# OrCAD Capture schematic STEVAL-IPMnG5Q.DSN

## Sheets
1 Inputs: size A4; title: STEVAL-IPMnG5Q; rev: 1.0; note: Draft
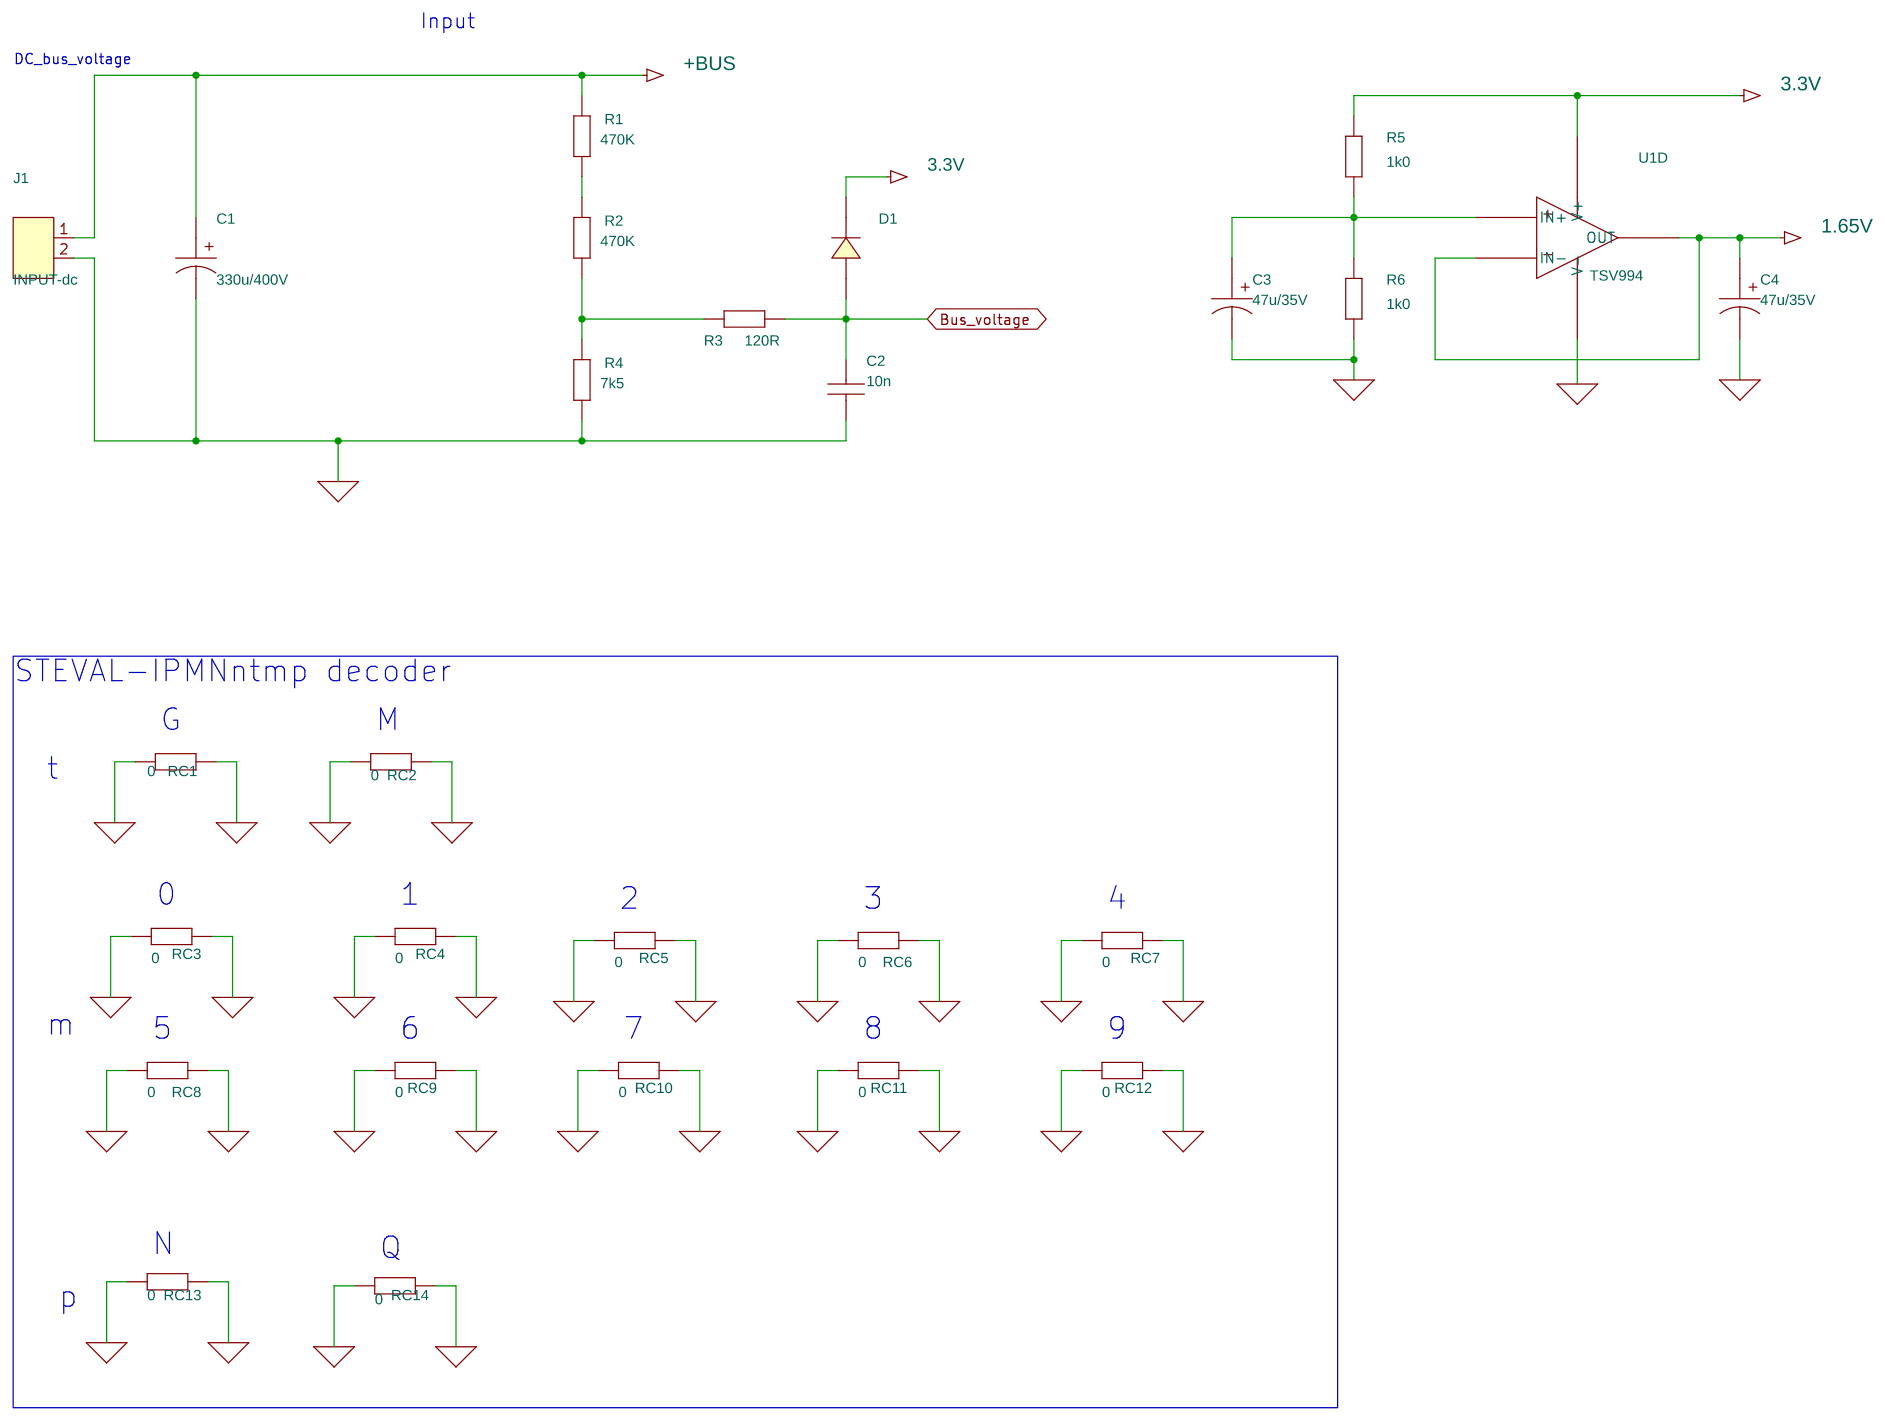
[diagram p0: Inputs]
2 Connectors: size A4
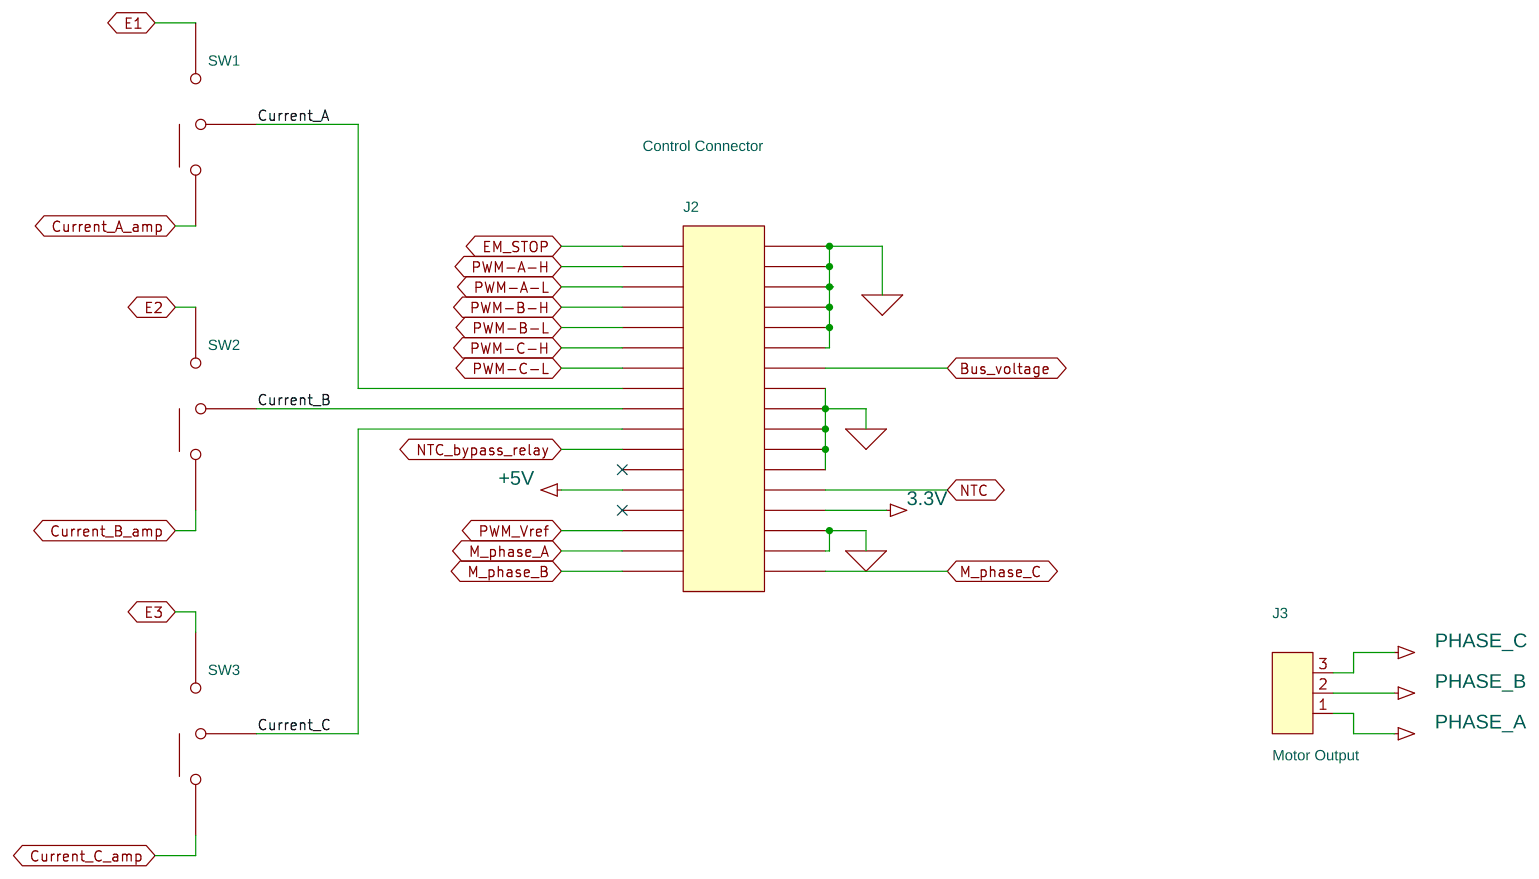
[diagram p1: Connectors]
3 Module: size Custom
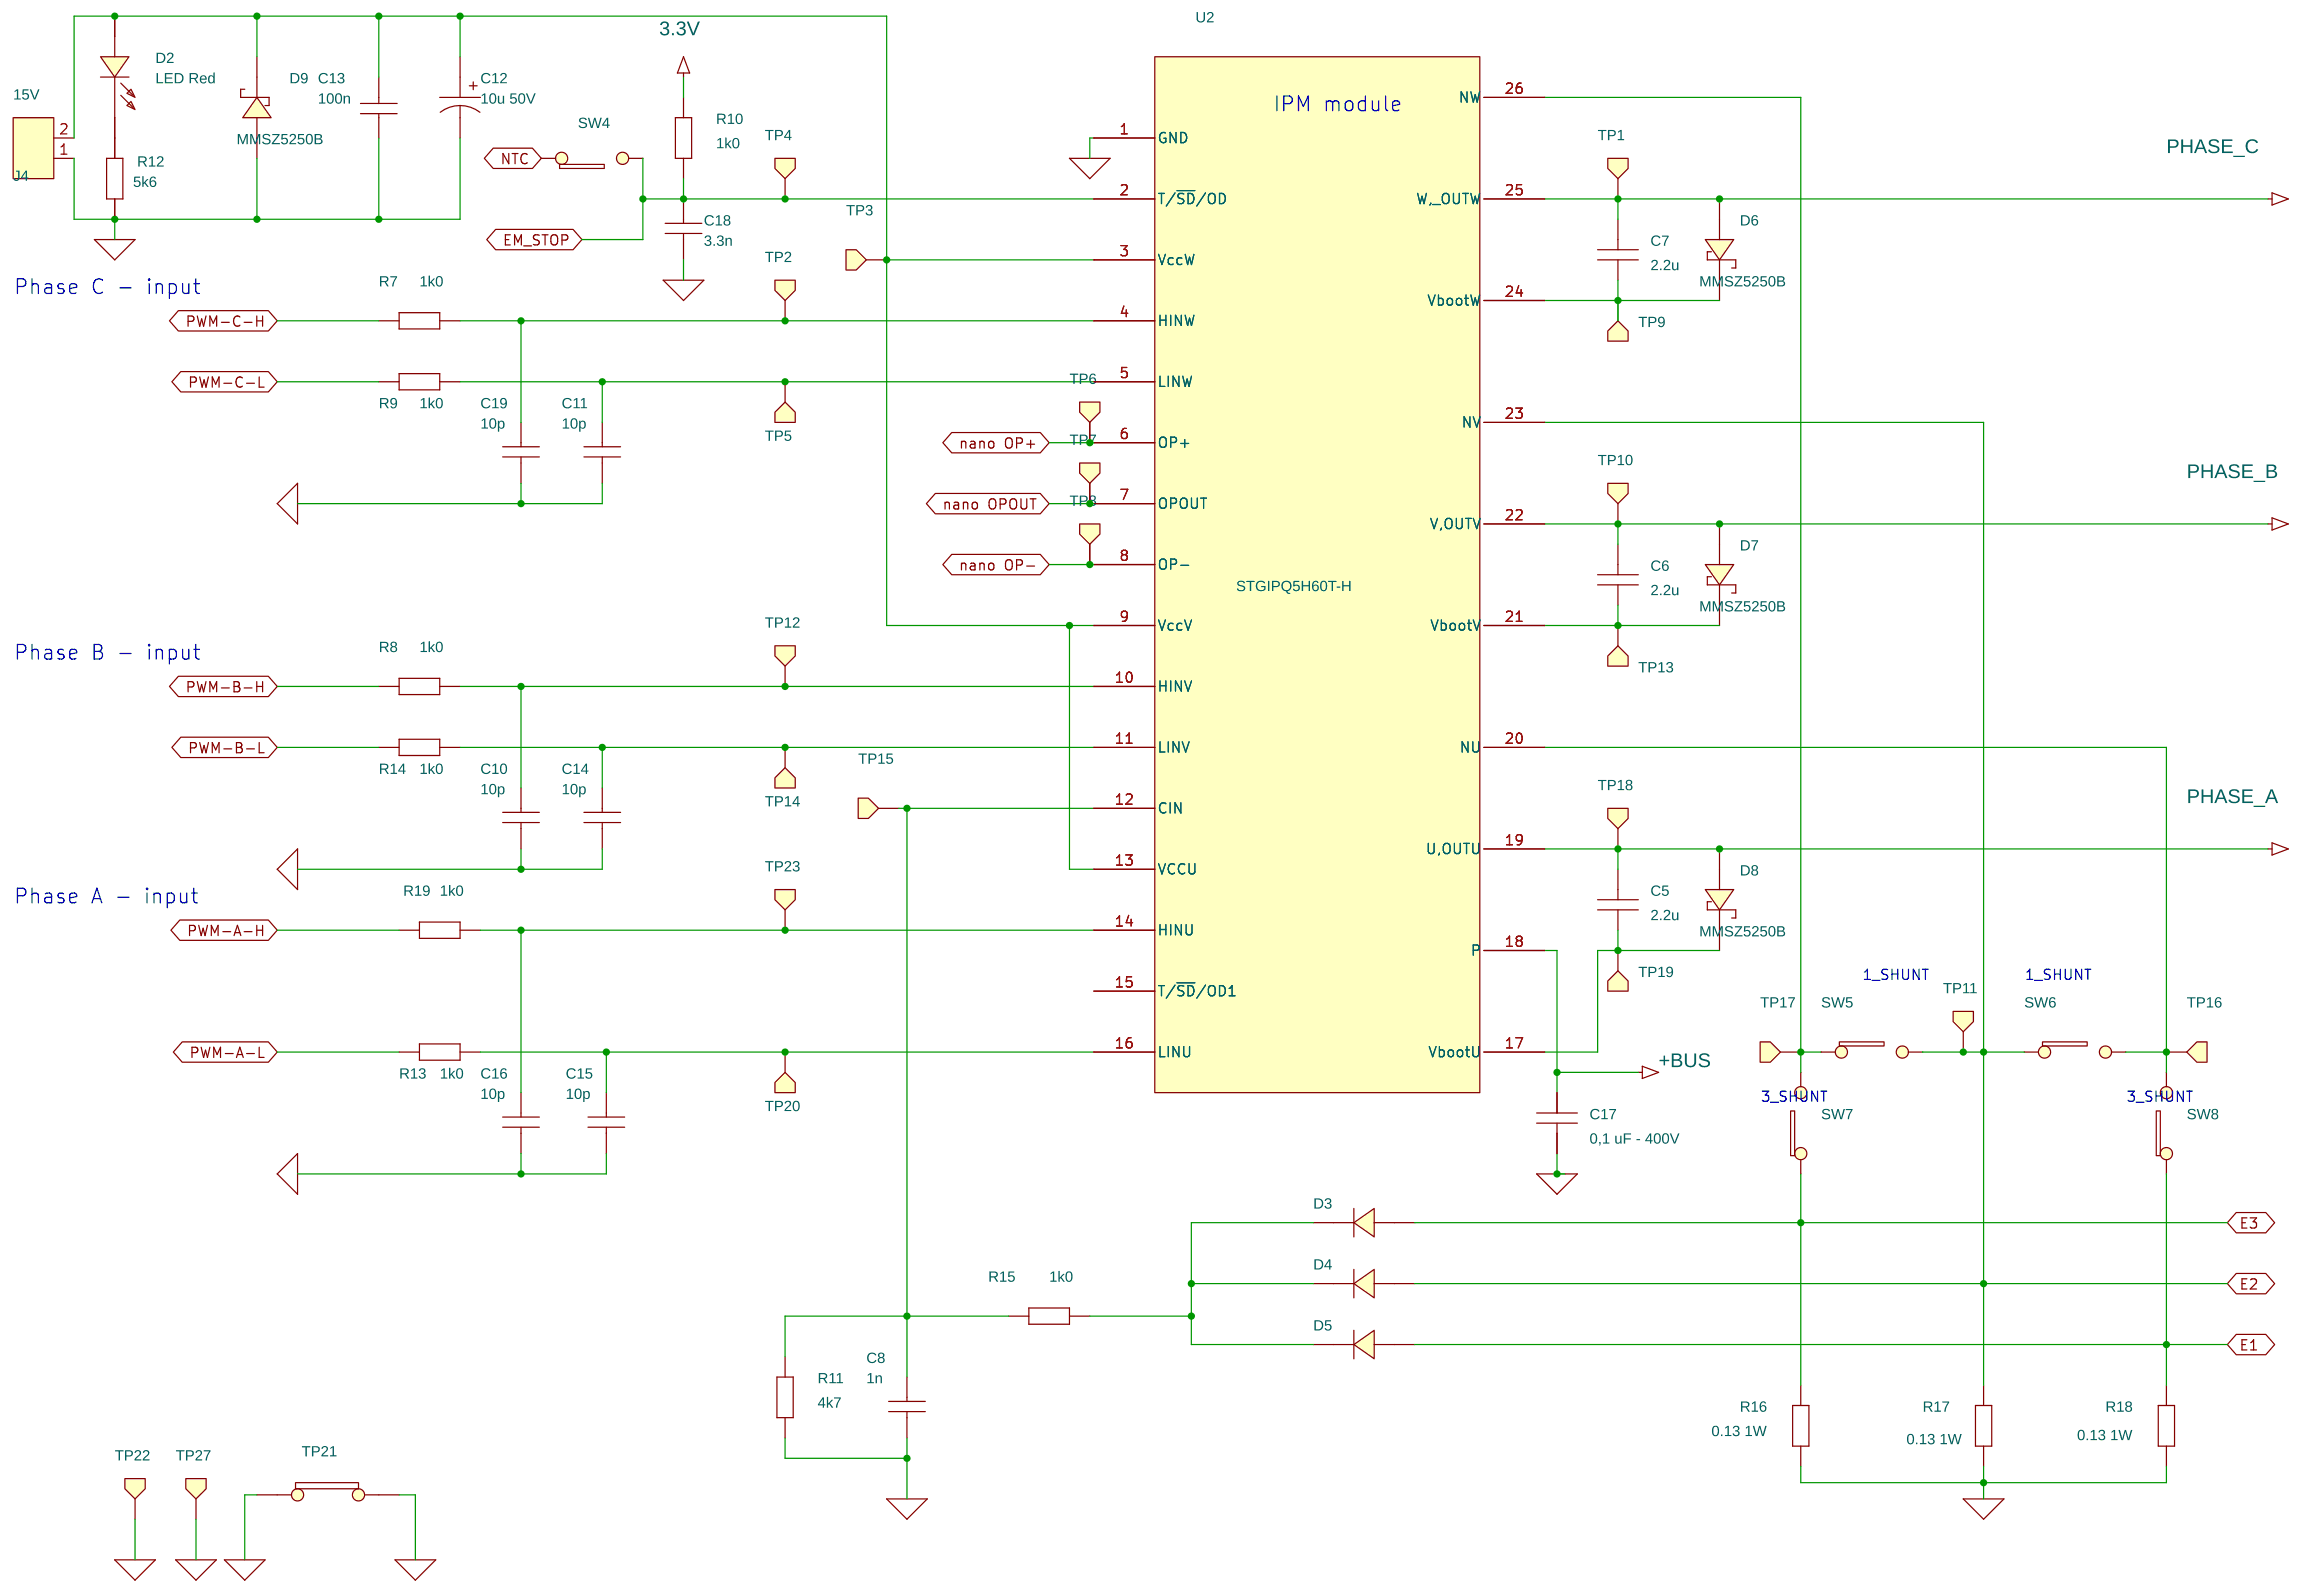
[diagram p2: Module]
4 Sensing: size A
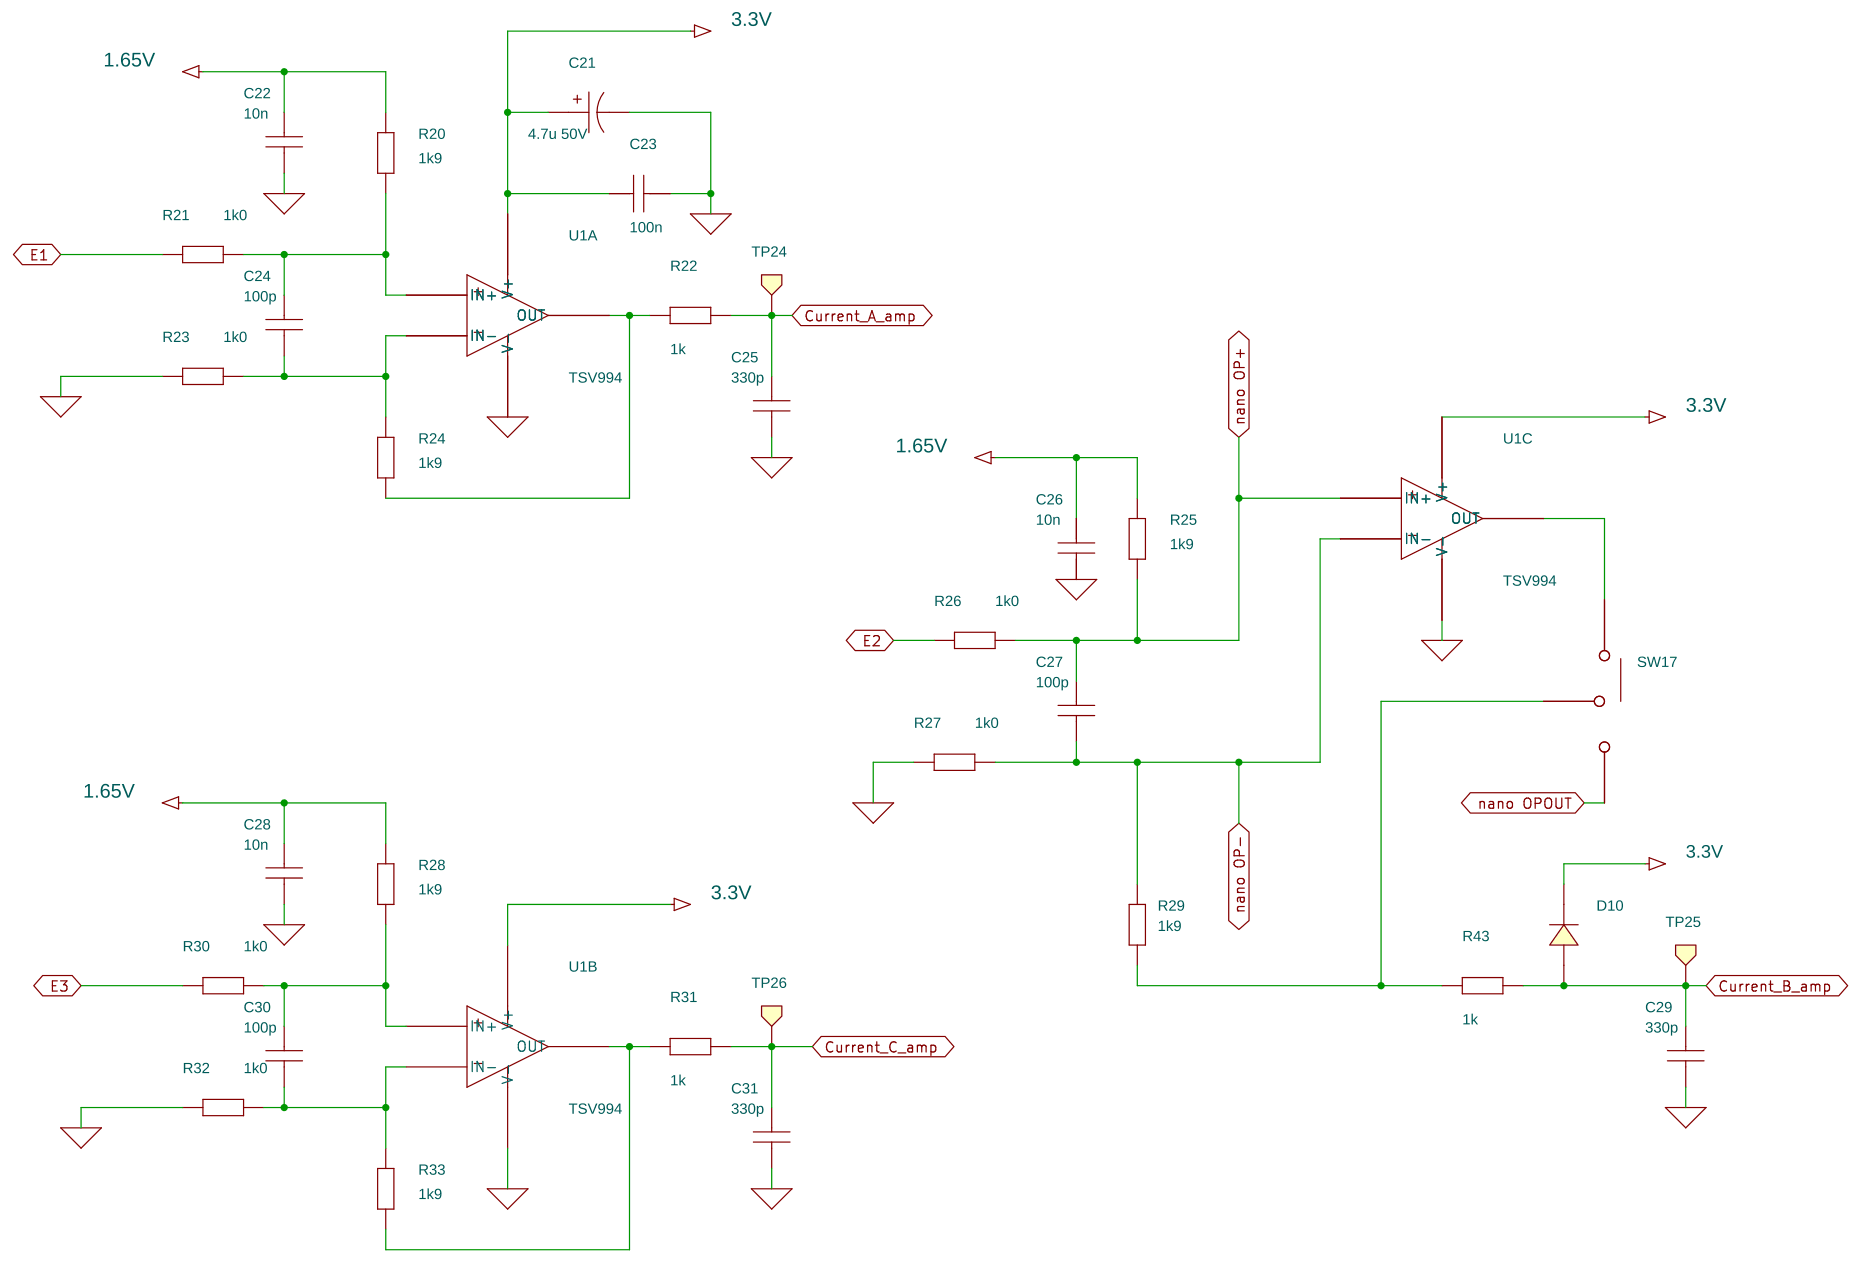
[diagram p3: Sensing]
5 Hall sensor: size A
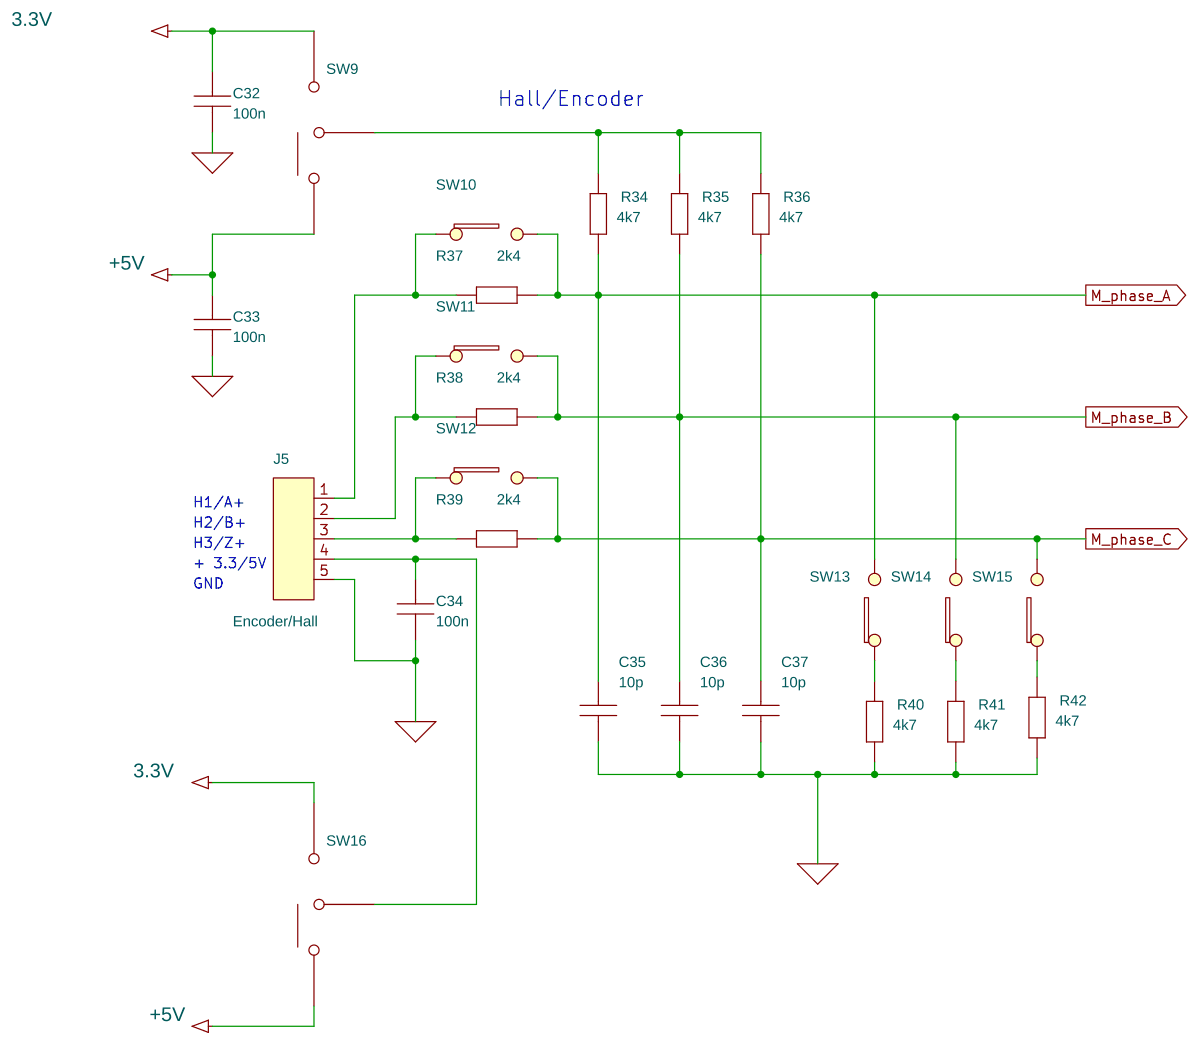
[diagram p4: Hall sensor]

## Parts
sheet Connectors
J2  Control Connector  [CONN_IDC_34_header]
J3  Motor Output  [mor3_7_62mm]
SW1  jump3  [strip3_100m_v]
SW2  jump3  [strip3_100m_v]
SW3  jump3  [strip3_100m_v]
sheet Hall sensor
C32  100n  [sm_c_1206]
C33  100n  [sm_c_1206]
C34  100n  [sm_c_1206]
C35  10p  [sm_c_1206]
C36  10p  [sm_c_1206]
C37  10p  [sm_c_1206]
J5  Encoder/Hall  [strip5_shrouded_headers_100m_v]
R34  4k7  [sm_r_1206]
R35  4k7  [sm_r_1206]
R36  4k7  [sm_r_1206]
R37  2k4  [sm_r_1206]
R38  2k4  [sm_r_1206]
R39  2k4  [sm_r_1206]
R40  4k7  [sm_r_1206]
R41  4k7  [sm_r_1206]
R42  4k7  [sm_r_1206]
SW9  jump3  [strip3_100m_v]
SW10  SW SLIDE-SPST_0  [jumper100m]
SW11  SW SLIDE-SPST_0  [jumper100m]
SW12  SW SLIDE-SPST_0  [jumper100m]
SW13  SW SLIDE-SPST_0  [jumper100m]
SW14  SW SLIDE-SPST_0  [jumper100m]
SW15  SW SLIDE-SPST_0  [jumper100m]
SW16  jump3  [strip3_100m_v]
sheet Inputs
C1  330u/400V  [cpcyl_d1400_ls393_75d]
C2  10n  [sm_c_1206]
C3  47u/35V  [cpcyl_d250_ls100_28d]
C4  47u/35V  [cpcyl_d250_ls100_28d]
D1  BAT48JFILM  [sm_sod-323]
J1  INPUT-dc  [mor2_7_62mm]
R1  470K  [sm_r_1206]
R2  470K  [sm_r_1206]
R3  120R  [sm_r_1206]
R4  7k5  [sm_r_1206]
R5  1k0  [sm_r_1206]
R6  1k0  [sm_r_1206]
RC1  0  [sm_r_0805]
RC2  0  [sm_r_0805]
RC3  0  [sm_r_0805]
RC4  0  [sm_r_0805]
RC5  0  [sm_r_0805]
RC6  0  [sm_r_0805]
RC7  0  [sm_r_0805]
RC8  0  [sm_r_0805]
RC9  0  [sm_r_0805]
RC10  0  [sm_r_0805]
RC11  0  [sm_r_0805]
RC12  0  [sm_r_0805]
RC13  0  [sm_r_0805]
RC14  0  [sm_r_0805]
U1  TSV994  [SO14]  (sections A,B,C,D)
sheet Module
C5  2.2u  [sm_r_1206]
C6  2.2u  [sm_r_1206]
C7  2.2u  [sm_r_1206]
C8  1n  [sm_c_1206]
C10  10p  [sm_c_1206]
C11  10p  [sm_c_1206]
C12  10u 50V  [cpcyl_d200_ls100_28d]
C13  100n  [sm_c_1206]
C14  10p  [sm_c_1206]
C15  10p  [sm_c_1206]
C16  10p  [sm_c_1206]
C17  0,1 uF - 400V  [smc1812]
C18  3.3n  [sm_c_1206]
C19  10p  [sm_c_1206]
D2  LED Red  [LED3mm]
D3  BAT48JFILM  [sm_sod-323]
D4  BAT48JFILM  [sm_sod-323]
D5  BAT48JFILM  [sm_sod-323]
D6  MMSZ5250B  [sod123]
D7  MMSZ5250B  [sod123]
D8  MMSZ5250B  [sod123]
D9  MMSZ5250B  [sod123]
J4  15V  [mor2_5_08mm]
R7  1k0  [sm_r_1206]
R8  1k0  [sm_r_1206]
R9  1k0  [sm_r_1206]
R10  1k0  [sm_r_1206]
R11  4k7  [sm_r_1206]
R12  5k6  [SM_R_1206]
R13  1k0  [sm_r_1206]
R14  1k0  [sm_r_1206]
R15  1k0  [sm_r_1206]
R16  0.13 1W  [smr2512]
R17  0.13 1W  [smr2512]
R18  0.13 1W  [smr2512]
R19  1k0  [sm_r_1206]
SW4  SW SLIDE-SPST_0  [siptm2002]
SW5  SW SLIDE-SPST_0  [sm_r_0603]
SW6  SW SLIDE-SPST_0  [sm_r_0603]
SW7  SW SLIDE-SPST_0  [sm_r_0603]
SW8  SW SLIDE-SPST_0  [sm_r_0603]
TP1  T POINT F  [testpoint_1mm]
TP2  T POINT F  [testpoint_1mm]
TP3  T POINT F  [testpoint_1mm]
TP4  T POINT F  [testpoint_1mm]
TP5  T POINT F  [testpoint_1mm]
TP6  T POINT F  [testpoint_1mm]
TP7  T POINT F  [testpoint_1mm]
TP8  T POINT F  [testpoint_1mm]
TP9  T POINT F  [testpoint_1mm]
TP10  T POINT F  [testpoint_1mm]
TP11  T POINT F  [testpoint_1mm]
TP12  T POINT F  [testpoint_1mm]
TP13  T POINT F  [testpoint_1mm]
TP14  T POINT F  [testpoint_1mm]
TP15  T POINT F  [testpoint_1mm]
TP16  T POINT F  [testpoint_1mm]
TP17  T POINT F  [testpoint_1mm]
TP18  T POINT F  [testpoint_1mm]
TP19  T POINT F  [testpoint_1mm]
TP20  T POINT F  [testpoint_1mm]
TP21  SW SLIDE-SPST_0  [JUMP1M5PITCH12X7]
TP22  T POINT F  [testpoint_1mm]
TP23  T POINT F  [testpoint_1mm]
TP27  T POINT F  [testpoint_1mm]
U2  STGIPQ5H60T-H  [N2dip26L]
sheet Sensing
C21  4.7u 50V  [cpcyl_d200_ls100_28d]
C22  10n  [sm_c_1206]
C23  100n  [sm_c_1206]
C24  100p  [sm_c_1206]
C25  330p  [sm_c_1206]
C26  10n  [sm_c_1206]
C27  100p  [sm_c_1206]
C28  10n  [sm_c_1206]
C29  330p  [sm_c_1206]
C30  100p  [sm_c_1206]
C31  330p  [sm_c_1206]
D10  BAT48JFILM  [sm_sod-323]
R20  1k9  [sm_r_1206]
R21  1k0  [sm_r_1206]
R22  1k  [sm_r_1206]
R23  1k0  [sm_r_1206]
R24  1k9  [sm_r_1206]
R25  1k9  [sm_r_1206]
R26  1k0  [sm_r_1206]
R27  1k0  [sm_r_1206]
R28  1k9  [sm_r_1206]
R29  1k9  [sm_r_1206]
R30  1k0  [sm_r_1206]
R31  1k  [sm_r_1206]
R32  1k0  [sm_r_1206]
R33  1k9  [sm_r_1206]
R43  1k  [sm_r_1206]
SW17  jump3  [strip3_100m_v]
TP24  T POINT F  [testpoint_1mm]
TP25  T POINT F  [testpoint_1mm]
TP26  T POINT F  [testpoint_1mm]

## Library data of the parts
J2 = CON34A
J3 = CON2_1
SW1-SW3 SW9 SW16 SW17 = jump3
C2 C8 C10 C11 C13-C16 C18 C19 C22-C37 = CAPACITOR_NON-POL
J5 = CON2_2
R34-R36 R40-R42 = R_1: %: 1%; power: 1/4W
R1-R15 R19-R33 R37-R39 R43 RC1-RC14 = R_0: %: 1%; power: 1/4W
SW4-SW8 SW10-SW15 = SW_SLIDE-SPST_0_v2
C1 = CAPACITOR_POL_2
C3 C4 C12 C21 = CAPACITOR_POL_1
D1 D10 = 1N4148_0
J1 J4 = CON2_0
U1 = TL084
C5-C7 = C_0: COMPFIXED: NO; COMPGROUP: 0; COMPHEIGHT: 0.000; COMPKEY: NO; COMPLOC: [1925.000,1150.000]; COMPLOCKED: NO; COMPROT: 0; COMPSIDE: TOP; DECOUPLER: NO; MEMORY: NO
C17 = C_0
D2 = F5F1_1
D3 = DIODE_1
D4 = DIODE_2
D5 = DIODE_3
D6 = MA745_TO_0
D7 = MA745_TO_1
D8 = MA745_TO_2
D9 = MA745_TO_3
R16-R18 = R_0: %: 1%; power: 1W
TP1-TP20 TP22-TP27 = T_POINT_F
TP21 = SW_SLIDE-SPST_4
U2 = 80C552_FP_19

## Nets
1.65V: C4.1(P) C22.1 C26.1 C28.1 R20.2 R25.2 R28.2 U1.13(IN-) U1.14(OUT)
3.3V: C21.1(P) C23.1 C32.1 D1.2(CATHODE) D10.2(CATHODE) J2.28 R5.2 R10.1 SW9.3 SW16.3 U1.4(V+)
+5V: C33.1 J2.25 SW9.1 SW16.1
GND_SIGNAL: C1.2(N) C2.2 C3.2(N) C4.2(N) C8.2 C10.2 C11.2 C12.2(N) C13.1 C14.2 C15.2 C16.2 C17.2 C18.2 C19.2 C21.2(N) C22.2 C23.2 C25.2 C26.2 C28.2 C29.2 C31.2 C32.2 C33.2 C34.2 C35.2 C36.2 C37.2 D9.1(ANODE) J1.2 J2.2 J2.4 J2.6 J2.8 J2.10 J2.12 J2.16 J2.18 J2.20 J2.22 J2.24 J2.30 J2.32 J4.1 J5.5 R4.2 R6.1 R11.1 R12.2 R16.2 R17.2 R18.2 R23.1 R27.1 R32.1 R40.2 R41.2 R42.2 RC1.1 RC1.2 RC2.1 RC2.2 RC3.1 RC3.2 RC4.1 RC4.2 RC5.1 RC5.2 RC6.1 RC6.2 RC7.1 RC7.2 RC8.1 RC8.2 RC9.1 RC9.2 RC10.1 RC10.2 RC11.1 RC11.2 RC12.1 RC12.2 RC13.1 RC13.2 RC14.1 RC14.2 TP21.1 TP21.2(NO) TP22.1(TP) TP27.1(TP) U1.11(V-) U2.1(GND)
+Bus: C1.1(P) C17.1 J1.1 R1.1 U2.18(P)
Bus_voltage: C2.1 D1.1(ANODE) J2.14 R3.2
Current_A: J2.15 SW1.2
Current_A_amp: C25.1 R22.1 SW1.1 TP24.1(TP)
Current_B: J2.17 SW2.2
Current_B_amp: C29.1 D10.1(ANODE) R43.1 SW2.1 TP25.1(TP)
Current_C: J2.19 SW3.2
Current_C_amp: C31.1 R31.1 SW3.1 TP26.1(TP)
E1: D5.1(A) R18.1 R21.1 SW1.3 SW8.1
E2: D4.1(A) R17.1 R26.1 SW2.3 SW5.2(NO) SW6.1 TP11.1(TP) U2.23(NV)
E3: D3.1(A) R16.1 R30.1 SW3.3 SW7.1
EM_STOP: C18.1 J2.1 R10.2 SW4.2(NO) TP4.1(TP) U2.2(T/~{SD}/OD)
M_phase_A: C35.1 J2.31 R34.2 R37.2 SW10.2(NO) SW13.2(NO)
M_phase_B: C36.1 J2.33 R35.2 R38.2 SW11.2(NO) SW14.2(NO)
M_phase_C: C37.1 J2.34 R36.2 R39.2 SW12.2(NO) SW15.2(NO)
nano OP+: C27.1 R25.1 R26.2 TP6.1(TP) U1.10(IN+) U2.6(OP+)
nano OP-: C27.2 R27.2 R29.1 TP8.1(TP) U1.9(IN-) U2.8(OP-)
nano OPOUT: SW17.3 TP7.1(TP) U2.7(OPOUT)
NTC: J2.26 SW4.1
NTC_bypass_relay: J2.21
phase_A: C5.2 D8.1(ANODE) J3.1 TP18.1(TP) U2.19(U,OUTU)
phase_B: C6.2 D7.1(ANODE) J3.2 TP10.1(TP) U2.22(V,OUTV)
phase_C: C7.2 D6.1(ANODE) J3.3 TP1.1(TP) U2.25(W,_OUTW)
PWM-A-H: J2.3 R19.1
PWM-A-L: J2.5 R13.1
PWM-B-H: J2.7 R8.1
PWM-B-L: J2.9 R14.1
PWM-C-H: J2.11 R7.1
PWM-C-L: J2.13 R9.1
PWM_Vref: J2.29
N6680355: R1.2 R2.1
N6680429: R2.2 R3.1 R4.1
N7418873: C19.1 R7.2 TP2.1(TP) U2.4(HINW)
N7419173: C11.1 R9.2 TP5.1(TP) U2.5(LINW)
N7419575: C15.1 R13.2 TP20.1(TP) U2.16(LINU)
N7419579: C16.1 R19.2 TP23.1(TP) U2.14(HINU)
N7419959: C14.1 R14.2 TP14.1(TP) U2.11(LINV)
N7419967: C10.1 R8.2 TP12.1(TP) U2.10(HINV)
N8602926: C24.1 R20.1 R21.2 U1.3(IN+)
N8603142: C24.2 R23.2 R24.1 U1.2(IN-)
N8608659: R22.2 R24.2 U1.1(OUT)
N8611164: C3.1(P) R5.1 R6.2 U1.12(IN+)
N8745560: D3.2(K) D4.2(K) D5.2(K) R15.2
N8758281: R29.2 R43.2 SW17.2
N8759020: R31.2 R33.2 U1.7(OUT)
N8759128: C30.1 R28.1 R30.2 U1.5(IN+)
N8759136: C30.2 R32.2 R33.1 U1.6(IN-)
N8769015: C34.1 J5.4 SW16.2
N8769177: R34.1 R35.1 R36.1 SW9.2
N8769259: J5.1 R37.1 SW10.1
N8769267: J5.2 R38.1 SW11.1
N8783110: J5.3 R39.1 SW12.1
N8796833: SW6.2(NO) SW8.2(NO) TP16.1(TP) U2.20(NU)
N8856248: C7.1 D6.2(CATHODE) TP9.1(TP) U2.24(VbootW)
N8857786: SW5.1 SW7.2(NO) TP17.1(TP) U2.26(NW)
N8867925: C8.1 R11.2 R15.1 TP15.1(TP) U2.12(CIN)
N8869100: C6.1 D7.2(CATHODE) TP13.1(TP) U2.21(VbootV)
N8869824: C5.1 D8.2(CATHODE) TP19.1(TP) U2.17(VbootU)
N8877212: C12.1(P) C13.2 D2.1(A) D9.2(CATHODE) J4.2 TP3.1(TP) U2.3(VccW) U2.9(VccV) U2.13(VCCU)
N8885403: SW17.1 U1.8(OUT)
N8906266: R42.1 SW15.1
N8906381: R41.1 SW14.1
N8906601: R40.1 SW13.1
N8949964: D2.2(C) R12.1

Not connected (* = marked no-connect by the designer): J2 23* 27*; U2 15(T/~{SD}/OD1)

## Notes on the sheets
sheet 1
- Input
- DC_bus_voltage
- STEVAL-IPMNntmp decoder
- G
- M
- t
- 0
- 1
- 2
- 3
- 4
- m
- 5
- 6
- 7
- 8
- 9
- N
- Q
- p
sheet 3
- IPM module
- Phase C - input
- Phase B - input
- Phase A - input
- 1_SHUNT
- 1_SHUNT
- 3_SHUNT
- 3_SHUNT
sheet 5
- Hall/Encoder
- H1/A+
- H2/B+
- H3/Z+
- + 3.3/5V
- GND
